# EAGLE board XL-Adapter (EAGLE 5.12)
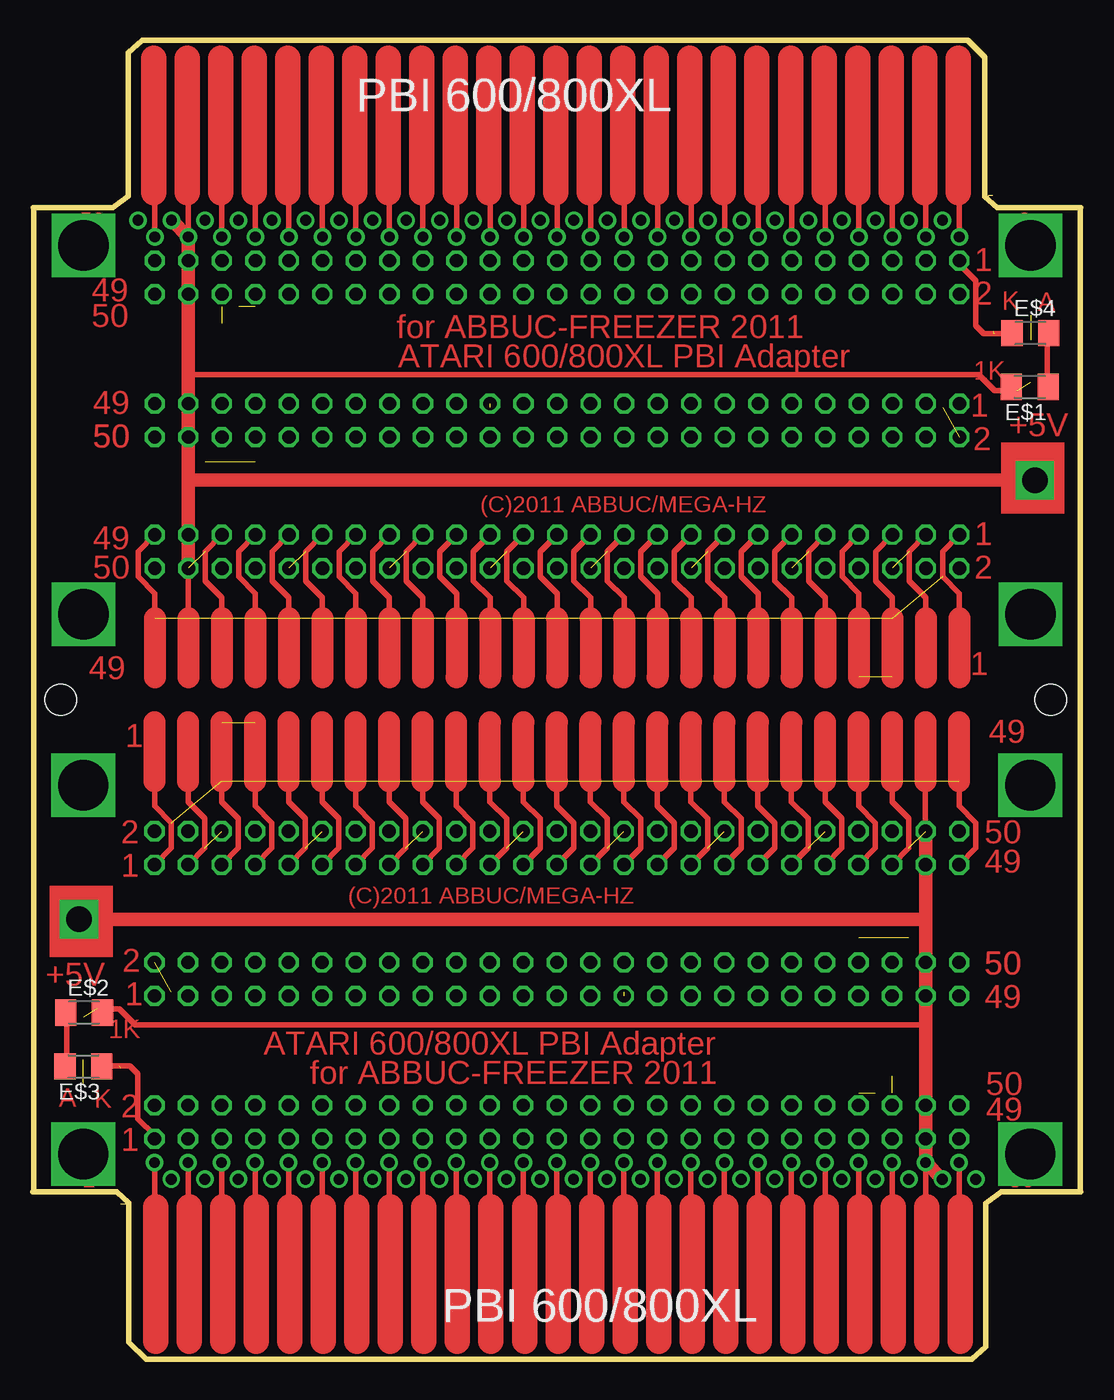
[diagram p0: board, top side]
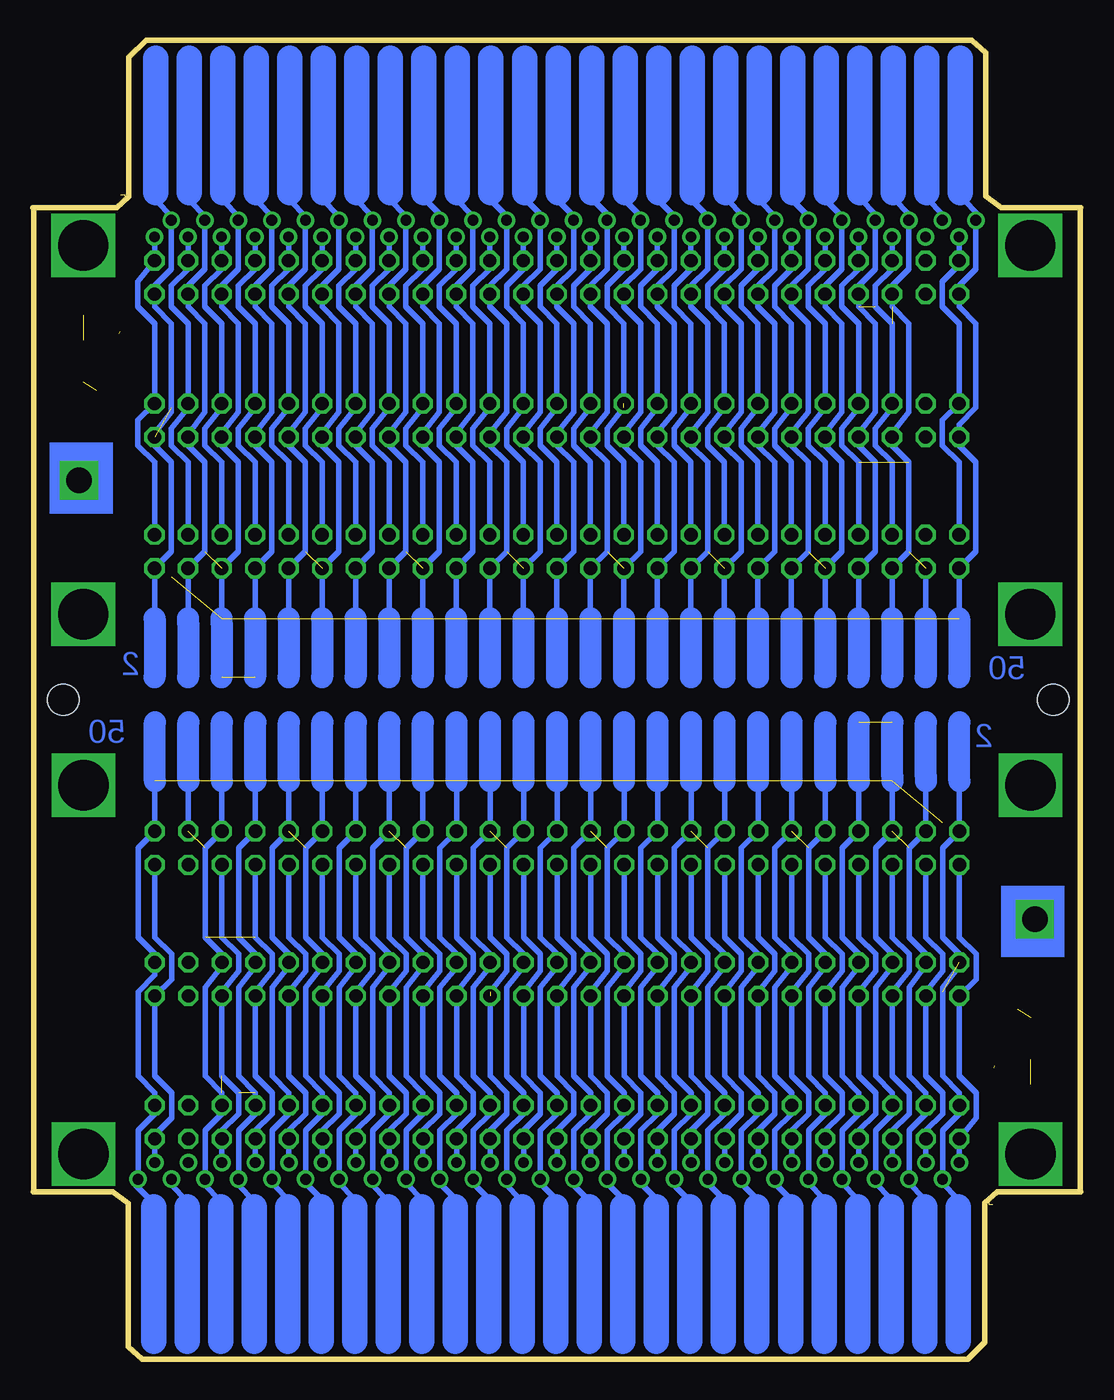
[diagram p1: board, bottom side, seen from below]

Size 79.4 x 100 mm. Coordinates in mm from the lower left corner, seen from the top.
Outline: 79.37,12.7 73.34,12.7 72.18,11.83 72.18,0.95 71.12,0 8.57,0 7.27,1.31 7.27,11.88 6.35,12.7 0,12.7
Outline: 0.02,87.3 6.05,87.3 7.22,88.16 7.22,99.04 8.28,100 70.82,100 72.13,98.69 72.13,88.11 73.04,87.3 79.4,87.3
Outline: 0.05,87.25 0.05,12.75
Outline: 79.35,87.25 79.35,12.75
Copper layers (1*16): Top 0.035mm / dielectric 1.5mm / Bottom 0.035mm
Design rules "ITead_rule": minimum track width 6mil, minimum drill 12mil, track to track 6mil, track to pad 6mil, pad to pad 6mil, via to via 6mil, smd to smd 0mil, copper to edge 10mil, drill to drill 10mil, minimum pad ring 10mil, minimum via ring 6mil, stop-mask expansion 2mil, vias tented up to drill 100mil, thermal gap 10mil
Net classes: 2 3.3: width 0.508 mm, clearance 0.254 mm
Holes 2.4 mm at 2.1,50 77.1,50

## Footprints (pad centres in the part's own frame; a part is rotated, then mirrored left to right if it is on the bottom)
M1206 = smd 1.6 x 2: 1 -1.4,0; 2 1.4,0
XL-PBI = drill 0.813 round: A0 31.115,-8.255; A1 29.845,-6.985; A2 28.575,-8.255; A3 27.305,-6.985; A4 26.035,-8.255; A5 24.765,-6.985; A6 23.495,-8.255; A7 20.955,-8.255; A8 19.685,-6.985; A9 18.415,-8.255; A10 17.145,-6.985; A11 15.875,-8.255; A12 14.605,-6.985; A13 13.335,-8.255; A14 12.065,-6.985; A15 9.525,-6.985; AUDIO -27.305,-8.255; CAS -17.145,-8.255; D0 8.255,-8.255; D1 6.985,-6.985; D2 5.715,-8.255; D3 4.445,-6.985; D4 3.175,-8.255; D5 1.905,-6.985; D6 0.635,-8.255; D7 -0.635,-6.985; EXT.B -13.335,-6.985; EXTSEL 32.385,-6.985; GND -28.575,-6.985; GND2 -18.415,-6.985; GND3 -5.715,-6.985; GND4 -3.175,-6.985; GND5 22.225,-6.985; GND6 33.655,-8.255; GND7 10.795,-8.255; GND8 -1.905,-8.255; GND9 -22.225,-8.255; IRQ -9.525,-8.255; MPD -19.685,-8.255; NC2 -6.985,-8.255; NC3 -12.065,-8.255; NC4 -14.605,-8.255; PHI2 -4.445,-8.255; RAS -20.955,-6.985; RDY -10.795,-6.985; REF -15.875,-6.985; RST -8.255,-6.985; RW -23.495,-6.985; VCC -24.765,-8.255; VCC1 -26.035,-6.985

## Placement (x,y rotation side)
E$1  [M1206]  75.53,73.71 180 top
E$2  [M1206]  3.87,26.29 0 top
E$3  [M1206]  3.82,22.21 180 top
E$4  [M1206]  75.57,77.78 0 top
U$1  XL-PBI  [XL-PBI]  36.53,93.33 0 top
U$3  XL-PBI  [XL-PBI]  42.86,6.67 180 top

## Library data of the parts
E$1-E$4 = rcl
U$1 U$3 = wf-atari

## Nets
N$1: U$3.EXTSEL
N$16: U$3.AUDIO
N$28: U$3.VCC U$3.VCC1
N$32: U$3.GND9
N$33: U$3.MPD
N$34: U$3.CAS
N$35: U$3.NC4
N$37: U$3.NC3
N$38: U$3.IRQ
N$48: U$3.NC2
N$81: U$3.PHI2
N$86: U$1.A2
N$88: U$3.GND8
N$89: U$3.D6
N$90: U$3.D4
N$91: U$3.D2
N$92: U$3.D0
N$93: U$3.GND7
N$94: U$3.A13
N$95: U$3.A11
N$96: U$3.A9
N$97: U$3.A7
N$98: U$3.A6
N$99: U$3.A4
N$102: U$3.RW
N$103: U$3.RAS
N$104: U$3.GND2
N$105: U$3.REF
N$106: U$3.EXT.B
N$107: U$3.RDY
N$108: U$3.RST
N$109: U$3.GND3
N$110: U$3.GND4
N$111: U$3.D7
N$112: U$3.D5
N$113: U$3.D3
N$114: U$3.D1
N$115: U$3.A15
N$116: U$3.A14
N$117: U$3.A12
N$118: U$3.A10
N$119: U$3.A8
N$120: U$3.GND5
N$122: U$3.A5
N$126: U$3.A1 U$3.A3
N$159: U$3.GND6
N$190: U$3.GND
N$238: U$1.A0
N$286: U$1.AUDIO
N$287: U$1.VCC U$1.VCC1
N$288: U$1.GND9
N$289: U$1.MPD
N$290: U$1.CAS
N$291: U$1.NC4
N$292: U$1.NC3
N$293: U$1.IRQ
N$294: U$1.NC2
N$295: U$1.PHI2
N$296: U$1.GND8
N$297: U$1.D6
N$298: U$1.D4
N$299: U$1.D2
N$300: U$1.D0
N$302: U$1.GND7
N$305: U$1.A13
N$306: U$1.A11
N$307: U$3.A2
N$309: U$1.A9
N$318: U$1.A7
N$329: U$1.A6
N$331: U$1.A4
N$334: U$1.EXTSEL
N$354: U$3.A0
N$356: U$1.A1 U$1.A3
N$358: U$1.A5
N$359: U$1.GND5
N$360: U$1.A8
N$361: U$1.A10
N$362: U$1.A12
N$363: U$1.A14
N$364: U$1.A15
N$365: U$1.D1
N$366: U$1.D3
N$367: U$1.D5
N$368: U$1.D7
N$369: U$1.GND4
N$370: U$1.GND3
N$371: U$1.RST
N$372: U$1.RW
N$373: U$1.RAS
N$374: U$1.GND2
N$375: U$1.REF
N$376: U$1.EXT.B
N$377: U$1.RDY
N$402: U$1.GND6
N$426: U$1.GND

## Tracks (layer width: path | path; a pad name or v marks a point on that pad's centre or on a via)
N$1  (via drill 1.02)  (1 unrouted)
  Bottom 0.406: 9.21,46.7 9.21,40.03 10.48,38.76 10.48,32 9.21,30.72 v9.21,30.09 | 10.48,27.87 10.48,21.48 9.21,20.21 v9.21,19.25 9.21,18.62 10.48,17.35 U$3.EXTSEL
N$16  (via drill 1.02)
  Bottom 0.406: U$3.AUDIO v70.17,16.72 70.17,17.03 68.9,18.3 68.9,20.21 70.17,21.48 70.17,27.55 68.9,28.82 68.9,30.72 70.17,32 v70.17,37.49
N$23  (via drill 1.02)
  other vias: 70.17,40.03
N$28  (via drill 1.02)  (1 unrouted)
  Top 0.406: 4.83,26.56 6.54,26.56 7.75,25.35 67.63,25.35 67.65,25.35
  Top 1.016: 67.63,26.91 67.63,25.35 v67.63,19.25 v67.63,16.72 U$3.VCC U$3.VCC1
N$29  (via drill 1.02, 1.93)
  Top 0.406: 67.63,43.52 67.63,43.4 67.6,43.73 67.6,40.46 67.63,37.49
  Top 1.016: v67.63,27.55 v67.63,30.09 67.63,33.36 | 4.13,33.36 3.18,33.36 | 4.13,33.36 67.63,33.36 | v3.49,33.36 4.13,33.36 | 67.63,33.36 67.63,37.49 v67.63,40.03
N$30  (via drill 1.02)
  other vias: 65.09,40.03
N$31  (via drill 1.02)
  other vias: 62.55,40.03
N$32  (via drill 1.02)
  Bottom 0.406: U$3.GND9 v65.09,16.72
N$33  (via drill 1.02)
  Bottom 0.406: U$3.MPD v62.55,16.72
N$34  (via drill 1.02)
  Bottom 0.406: U$3.CAS v60.01,16.72
N$35  (via drill 1.02)
  Bottom 0.406: U$3.NC4 v57.47,16.72
N$36  (via drill 1.02)
  other vias: 60.01,40.03
N$37  (via drill 1.02)
  Bottom 0.406: U$3.NC3 v54.93,16.72
N$38  (via drill 1.02)
  Bottom 0.406: U$3.IRQ v52.39,16.72
N$39  (via drill 1.02)
  other vias: 57.47,40.03
N$40  (via drill 1.02)
  other vias: 54.93,40.03
N$41  (via drill 1.02)
  other vias: 52.39,40.03
N$42  (via drill 1.02)
  other vias: 49.85,40.03
N$43  (via drill 1.02)
  other vias: 47.31,40.03
N$44  (via drill 1.02)
  other vias: 44.77,40.03
N$45  (via drill 1.02)
  other vias: 42.23,40.03
N$46  (via drill 1.02)
  other vias: 39.69,40.03
N$47  (via drill 1.02)
  other vias: 37.15,40.03
N$48  (via drill 1.02)
  Bottom 0.406: U$3.NC2 v49.85,16.72
N$49  (via drill 1.02)
  other vias: 34.61,40.03
N$50  (via drill 1.02)
  other vias: 32.07,40.03
N$51  (via drill 1.02)
  other vias: 29.53,40.03
N$52  (via drill 1.02)
  other vias: 26.99,40.03
N$53  (via drill 1.02)
  other vias: 24.45,40.03
N$54  (via drill 1.02)
  other vias: 21.91,40.03
N$55  (via drill 1.02)
  other vias: 19.37,40.03
N$56  (via drill 1.02)
  other vias: 16.83,40.03
N$57  (via drill 3.81)
  other vias: 75.59,56.47
N$58
  Top 0.406: 19.37,43.84 19.37,42.25 20.64,40.98 20.64,38.76 19.37,37.49
N$59
  Top 0.406: 16.83,37.49 18.1,38.76 18.1,40.66 16.83,41.94 16.83,43.84
N$60
  Top 0.406: 21.91,43.52 21.91,42.25 23.18,40.98 23.18,38.76 21.91,37.49
N$61  (via drill 3.81)
  other vias: 3.83,56.47
N$62
  Top 0.406: 26.99,43.84 26.99,42.25 28.26,40.98 28.26,38.76 26.99,37.49
N$63
  Top 0.406: 24.45,37.49 25.72,38.76 25.72,40.66 24.45,41.94 24.45,43.84
N$64
  Top 0.406: 29.53,43.52 29.53,42.25 30.8,40.98 30.8,38.76 29.53,37.49
N$65  (via drill 3.81)
  other vias: 3.83,84.44
N$66
  Top 0.406: 34.61,43.84 34.61,42.25 35.88,40.98 35.88,38.76 34.61,37.49
N$67
  Top 0.406: 32.07,37.49 33.34,38.76 33.34,40.66 32.07,41.94 32.07,43.84
N$68
  Top 0.406: 37.15,43.52 37.15,42.25 38.42,40.98 38.42,38.76 37.15,37.49
N$69  (via drill 3.81)
  other vias: 75.59,84.44
N$70
  Top 0.406: 42.23,43.84 42.23,42.25 43.5,40.98 43.5,38.76 42.23,37.49
N$71
  Top 0.406: 39.69,37.49 40.96,38.76 40.96,40.66 39.69,41.94 39.69,43.84
N$72
  Top 0.406: 44.77,43.52 44.77,42.25 46.04,40.98 46.04,38.76 44.77,37.49
N$73  (via drill 1.02)
  other vias: 11.77,62.51
N$74
  Top 0.406: 49.85,43.84 49.85,42.25 51.12,40.98 51.12,38.76 49.85,37.49
N$75
  Top 0.406: 47.31,37.49 48.58,38.76 48.58,40.66 47.31,41.94 47.31,43.84
N$76
  Top 0.406: 52.39,43.52 52.39,42.25 53.66,40.98 53.66,38.76 52.39,37.49
N$77  (via drill 1.02)
  Bottom 0.406: 54.95,83.28 54.95,82.64 56.22,81.38 56.22,79.79 54.95,78.52 54.95,72.44 | 54.95,72.44 54.95,72.76 | 54.95,72.44 54.95,72.13 56.22,70.54 56.22,69.27 54.95,68 v54.95,62.51
N$78
  Top 0.406: 57.47,43.84 57.47,42.25 58.74,40.98 58.74,38.76 57.47,37.49
N$79  (via drill 1.02)
  Bottom 0.406: 60.03,83.28 60.03,82.64 61.3,81.38 61.3,79.79 60.03,78.52 60.03,72.13 61.3,70.54 61.3,69.27 60.03,68 v60.03,62.51
N$80
  Top 0.406: 54.93,37.49 56.2,38.76 56.2,40.66 54.93,41.94 54.93,43.84
N$81  (via drill 1.02)
  Bottom 0.406: U$3.PHI2 v47.31,16.72
N$82
  Top 0.406: 60.01,43.52 60.01,42.25 61.28,40.98 61.28,38.76 60.01,37.49
N$83  (via drill 1.02)
  Top 0.406: 67.65,56.16 67.65,57.74 66.38,59.01 66.38,61.24 v67.65,62.51
  Top 1.676: 67.65,56.16 67.65,51.71
N$84
  Top 0.406: 65.09,43.84 65.09,42.25 66.36,40.98 66.36,38.76 65.09,37.49
N$85
  Top 0.406: 62.55,37.49 63.82,38.76 63.82,40.66 62.55,41.94 62.55,43.84
N$86  (via drill 1.02)
  Top 0.406: 65.11,56.47 65.11,57.74 63.84,59.01 63.84,61.24 v65.11,62.51
  Bottom 0.406: 65.11,62.82 v65.11,62.51 65.11,68 66.38,69.27 66.38,70.54 65.11,72.13 65.11,72.44 | U$1.A2 v65.11,83.28 65.11,82.64 66.38,81.38 66.38,79.79 65.11,78.52 65.11,72.44 | 65.11,72.44 65.11,72.76
N$87
  Top 0.406: 70.17,37.49 71.44,38.76 71.44,40.66 70.17,41.94 70.17,43.84
N$88  (via drill 1.02)
  Bottom 0.406: U$3.GND8 v44.77,16.72
N$89  (via drill 1.02)
  Bottom 0.406: U$3.D6 v42.23,16.72
N$90  (via drill 1.02)
  Bottom 0.406: U$3.D4 v39.69,16.72
N$91  (via drill 1.02)
  Bottom 0.406: U$3.D2 v37.15,16.72
N$92  (via drill 1.02)
  Bottom 0.406: U$3.D0 v34.61,16.72
N$93  (via drill 1.02)
  Bottom 0.406: U$3.GND7 v32.07,16.72
N$94  (via drill 1.02)
  Bottom 0.406: U$3.A13 v29.53,16.72
N$95  (via drill 1.02)
  Bottom 0.406: U$3.A11 v26.99,16.72
N$96  (via drill 1.02)
  Bottom 0.406: U$3.A9 v24.45,16.72
N$97  (via drill 1.02)
  Bottom 0.406: U$3.A7 v21.91,16.72
N$98  (via drill 1.02)
  Bottom 0.406: U$3.A6 v19.37,16.72
N$99  (via drill 1.02)
  Bottom 0.406: U$3.A4 v16.83,16.72 16.83,17.35 15.56,18.62 15.56,20.21 16.83,21.48 16.83,27.87 15.56,29.45 15.56,30.72 16.83,32 v16.83,37.49
N$100  (via drill 1.02)
  other vias: 9.23,72.44
N$101  (via drill 1.02)
  other vias: 14.31,72.44
N$102
  Bottom 0.406: U$3.RW 66.36,17.35
N$103
  Bottom 0.406: U$3.RAS 63.82,17.35
N$104
  Bottom 0.406: U$3.GND2 61.28,17.35
N$105
  Bottom 0.406: U$3.REF 58.74,17.35
N$106
  Bottom 0.406: U$3.EXT.B 56.2,17.35
N$107
  Bottom 0.406: U$3.RDY 53.66,17.35
N$108
  Bottom 0.406: U$3.RST 51.12,17.35
N$109
  Bottom 0.406: U$3.GND3 48.58,17.35
N$110
  Bottom 0.406: U$3.GND4 46.04,17.35
N$111
  Bottom 0.406: U$3.D7 43.5,17.35
N$112
  Bottom 0.406: U$3.D5 40.96,17.35
N$113
  Bottom 0.406: U$3.D3 38.42,17.35
N$114
  Bottom 0.406: U$3.D1 35.88,17.35
N$115
  Bottom 0.406: U$3.A15 33.34,17.35
N$116
  Bottom 0.406: U$3.A14 30.8,17.35
N$117
  Bottom 0.406: U$3.A12 28.26,17.35
N$118
  Bottom 0.406: U$3.A10 25.72,17.35
N$119
  Bottom 0.406: U$3.A8 23.18,17.35
N$120
  Bottom 0.406: U$3.GND5 20.64,17.35
N$121  (via drill 1.02)
  other vias: 16.85,72.44
N$122
  Bottom 0.406: U$3.A5 18.1,17.35
N$123
  Bottom 0.406: 18.1,13.65 18.1,17.35 16.83,18.62 16.83,20.21 18.1,21.48
N$124  (via drill 1.02)
  other vias: 19.39,72.44
N$125
  Bottom 0.406: 20.64,13.65 20.64,17.35 19.37,18.62 19.37,20.21 20.64,21.48
N$126  (via drill 1.02)  (23 unrouted)
  Bottom 0.406: U$3.A1 13.02,17.35 11.75,18.62 v11.75,19.25 11.75,20.21 13.02,21.48 13.02,28.18 11.73,29.94 11.75,30.72 13.02,32 13.02,38.76 v11.75,40.03 11.75,44.16 | 14.29,44.16 v14.29,40.03 15.56,38.76 15.56,32 14.29,30.72 14.29,29.77 15.56,28.18 15.56,21.48 14.29,20.21 v14.29,19.25 14.29,18.62 15.56,17.35 U$3.A3
  Bottom 1.676: 70.17,43.84 70.17,48.28 | 67.63,43.84 67.63,48.28 | 65.09,43.84 65.09,48.28 | 62.55,43.84 62.55,48.28 | 60.01,43.84 60.01,48.28 | 57.47,43.84 57.47,48.28 | 54.93,43.84 54.93,48.28 | 52.39,43.84 52.39,48.28 | 49.85,43.84 49.85,48.28 | 47.31,43.84 47.31,48.28 | 44.77,43.84 44.77,48.28 | 42.23,43.84 42.23,48.28 | 39.69,43.84 39.69,48.28 | 37.15,43.84 37.15,48.28 | 34.61,43.84 34.61,48.28 | 32.07,43.84 32.07,48.28 | 29.53,43.84 29.53,48.28 | 26.99,43.84 26.99,48.28 | 24.45,43.84 24.45,48.28 | 21.91,43.84 21.91,48.28 | 19.37,43.84 19.37,48.28 | 16.83,43.84 16.83,48.28 | 11.75,43.84 11.75,44.16 11.75,48.28 | 14.29,43.84 14.29,44.16 14.29,48.28
N$127  (via drill 1.02)
  other vias: 21.93,72.44
N$128  (via drill 1.02)
  other vias: 24.47,72.44
N$129
  Bottom 0.406: 23.18,13.65 23.18,17.35 21.91,18.62 21.91,20.21 23.18,21.48
N$130
  Bottom 0.406: 25.72,13.65 25.72,17.35 24.45,18.62 24.45,20.21 25.72,21.48
N$131  (via drill 1.02)
  other vias: 27.01,72.44
N$132  (via drill 1.02)
  Bottom 0.406: 29.53,16.72 29.53,17.35 28.26,18.62 28.26,20.21 29.53,21.48 29.53,27.87 28.26,29.45 28.26,30.72 29.53,32 v29.53,37.49
N$133
  Bottom 0.406: 28.26,13.65 28.26,17.35 26.99,18.62 26.99,20.21 28.26,21.48
N$134
  Bottom 0.406: 30.8,13.65 30.8,17.35 29.53,18.62 29.53,20.21 30.8,21.48
N$135  (via drill 1.02)
  other vias: 29.55,72.44
N$136  (via drill 1.02)
  other vias: 32.09,72.44
N$137
  Bottom 0.406: 33.34,13.65 33.34,17.35 32.07,18.62 32.07,20.21 33.34,21.48
N$138
  Bottom 0.406: 35.88,13.65 35.88,17.35 34.61,18.62 34.61,20.21 35.88,21.48
N$139  (via drill 1.02)
  other vias: 37.17,72.44
N$140  (via drill 1.02)
  Bottom 0.406: 39.69,16.72 39.69,17.35 38.42,18.62 38.42,20.21 39.69,21.48 39.69,27.87 38.42,29.45 38.42,30.72 39.69,32 v39.69,37.49
N$141
  Bottom 0.406: 38.42,13.65 38.42,17.35 37.15,18.62 37.15,20.21 38.42,21.48
N$142
  Bottom 0.406: 40.96,13.65 40.96,17.35 39.69,18.62 39.69,20.21 40.96,21.48
N$143  (via drill 1.02)
  other vias: 39.71,72.44
N$144  (via drill 1.02)  (1 unrouted)
  Bottom 0.406: 44.77,16.72 44.77,17.35 43.5,18.62 43.5,20.21 44.77,21.48 44.77,27.87 43.5,29.45 43.5,30.72 44.77,32 v44.77,37.49
  other vias: 44.77,27.55
N$145
  Bottom 0.406: 43.5,13.65 43.5,17.35 42.23,18.62 42.23,20.21 43.5,21.48
N$146
  Bottom 0.406: 46.04,13.65 46.04,17.35 44.77,18.62 44.77,20.21 46.04,21.48
N$147  (via drill 1.02)
  other vias: 42.25,72.44
N$148  (via drill 1.02)
  Bottom 0.406: 49.85,16.72 49.85,17.35 48.58,18.62 48.58,20.21 49.85,21.48 49.85,27.87 48.58,29.45 48.58,30.72 49.85,32 v49.85,37.49
N$149
  Bottom 0.406: 48.58,13.65 48.58,17.35 47.31,18.62 47.31,20.21 48.58,21.48
N$150
  Bottom 0.406: 51.12,13.65 51.12,17.35 49.85,18.62 49.85,20.21 51.12,21.48
N$151  (via drill 1.02)
  other vias: 44.79,72.44
N$152  (via drill 1.02)
  Bottom 0.406: 54.93,16.72 54.93,17.35 53.66,18.62 53.66,20.21 54.93,21.48 54.93,27.87 53.66,29.45 53.66,30.72 54.93,32 v54.93,37.49
N$153
  Bottom 0.406: 53.66,13.65 53.66,17.35 52.39,18.62 52.39,20.21 53.66,21.48
N$154
  Bottom 0.406: 56.2,13.65 56.2,17.35 54.93,18.62 54.93,20.21 56.2,21.48
N$155  (via drill 1.02)
  other vias: 47.33,72.44
N$156  (via drill 1.02)
  Bottom 0.406: 60.01,16.72 60.01,17.35 58.74,18.62 58.74,20.21 60.01,21.48 60.01,27.87 58.74,29.45 58.74,30.72 60.01,32 v60.01,37.49
N$157
  Bottom 0.406: 58.74,13.65 58.74,17.35 57.47,18.62 57.47,20.21 58.74,21.48
N$158
  Bottom 0.406: 61.28,13.65 61.28,17.35 60.01,18.62 60.01,20.21 61.28,21.48
N$159  (via drill 1.02)  (24 unrouted)
  Top 0.406: v9.21,37.49 10.48,38.76 10.48,40.66 9.21,41.94 9.21,43.84 | v9.21,16.72 9.21,16.99 7.95,18.25 7.95,21.65 7.35,22.25 6.55,22.25 5.25,22.25
  Top 1.676: 9.21,43.84 9.21,48.28 | 14.29,43.84 14.29,48.28 | 16.83,43.84 16.83,48.28 | 19.37,43.84 19.37,48.28 | 21.91,43.84 21.91,48.28 | 24.45,43.84 24.45,48.28 | 26.99,43.84 26.99,48.28 | 29.53,43.84 29.53,48.28 | 32.07,43.84 32.07,48.28 | 34.61,43.84 34.61,48.28 | 37.15,43.84 37.15,48.28 | 39.69,43.84 39.69,48.28 | 42.23,43.84 42.23,48.28 | 44.77,43.84 44.77,48.28 | 47.31,43.84 47.31,48.28 | 49.85,43.84 49.85,48.28 | 52.39,43.84 52.39,48.28 | 54.93,43.84 54.93,48.28 | 57.47,43.84 57.47,48.28 | 60.01,43.84 60.01,48.28 | 62.55,43.84 62.55,48.28 | 65.09,43.84 65.09,48.28 | 67.63,43.84 67.63,48.28 | 70.17,43.84 70.17,48.28
  Bottom 0.406: 9.21,32 9.21,37.17 | 7.94,30.72 7.94,29.14 | 9.21,26.96 9.21,27.19 | 9.21,32 v9.21,37.49 | 7.94,30.72 9.21,32 | 7.94,30.72 7.94,28.82 v9.21,27.55 9.21,26.96 | 9.21,26.96 9.21,21.48 7.94,20.21 7.94,18.3 v9.21,16.72 U$3.GND6
N$160
  Bottom 0.406: 11.75,27.23 11.75,27.87 10.48,29.45 10.48,30.72 11.75,32 11.75,37.17
N$161  (via drill 1.02)
  other vias: 49.87,72.44
N$162
  Top 1.016: 67.63,27.23 67.63,29.77
N$163  (via drill 1.02)
  other vias: 52.41,72.44
N$164  (via drill 1.02)
  other vias: 54.95,72.44
N$165  (via drill 1.02)
  other vias: 57.49,72.44
N$166
  Bottom 0.406: 10.48,38.44 10.48,32 9.21,30.72 9.21,29.77 10.48,28.18 10.48,25.92
N$167  (via drill 1.02)
  other vias: 60.03,72.44
N$168  (via drill 1.02)
  other vias: 62.57,72.44
N$169
  Bottom 0.406: 18.1,21.48 18.1,27.87
N$170
  Bottom 0.406: 20.64,21.48 20.64,27.87
N$171
  Bottom 0.406: 23.18,21.48 23.18,27.87
N$172
  Bottom 0.406: 25.72,21.48 25.72,27.87
N$173
  Bottom 0.406: 28.26,21.48 28.26,27.87
N$174
  Bottom 0.406: 30.8,21.48 30.8,27.87
N$175
  Bottom 0.406: 33.34,21.48 33.34,27.87
N$176
  Bottom 0.406: 35.88,21.48 35.88,27.87
N$177
  Bottom 0.406: 38.42,21.48 38.42,27.87
N$178
  Bottom 0.406: 40.96,21.48 40.96,27.87
N$179
  Bottom 0.406: 43.5,21.48 43.5,27.87
N$180
  Bottom 0.406: 46.04,21.48 46.04,27.87
N$181
  Bottom 0.406: 48.58,21.48 48.58,27.87
N$182  (via drill 1.02)
  other vias: 11.75,30.09
N$183
  Bottom 0.406: 51.12,21.48 51.12,27.87
N$184
  Bottom 0.406: 66.36,21.48 66.36,28.18
N$185
  Bottom 0.406: 63.82,21.48 63.82,28.18
N$186
  Bottom 0.406: 61.28,21.48 61.28,27.87
N$187
  Bottom 0.406: 58.74,21.48 58.74,27.87
N$188
  Bottom 0.406: 56.2,21.48 56.2,27.87
N$189
  Bottom 0.406: 53.66,21.48 53.66,27.87
N$190
  Bottom 0.406: U$3.GND 71.44,17.35 70.17,18.62 70.17,20.21 71.44,21.48 71.44,27.87 70.17,29.14 70.17,30.72 71.44,32 71.44,38.76 70.17,40.03 70.17,46.7
N$191  (via drill 1.02)
  Bottom 0.406: 21.91,16.72 21.91,17.35 20.64,18.62 20.64,20.21 21.91,21.48 21.91,27.87 20.64,29.45 20.64,30.72 21.91,32 v21.91,37.49
N$192  (via drill 1.02)
  other vias: 65.11,72.44
N$193
  Bottom 0.406: 18.1,21.48 18.1,28.18 16.83,29.77 16.83,30.72 18.1,32 18.1,38.76 16.83,40.03 16.83,46.7
N$194  (via drill 1.02)
  other vias: 9.23,69.91
N$195  (via drill 1.02)
  Bottom 0.406: 26.99,16.72 26.99,17.35 25.72,18.62 25.72,20.21 26.99,21.48 26.99,27.87 25.72,29.45 25.72,30.72 26.99,32 v26.99,37.49
N$196  (via drill 1.02)
  other vias: 14.31,69.91
N$197  (1 unrouted)
  Bottom 0.406: 23.18,21.48 23.18,28.18 21.91,29.77 21.91,30.72 23.18,32 23.18,38.76 21.91,40.03 21.91,44.16 | 20.64,21.48 20.64,28.18 19.37,29.77 19.37,30.72 20.64,32 20.64,38.76 19.37,40.03 19.37,44.16
N$198
  Bottom 0.406: 25.72,21.48 25.72,28.18 24.45,29.77 24.45,30.72 25.72,32 25.72,38.76 24.45,40.03 24.45,46.7
N$199  (via drill 1.02)
  Bottom 0.406: 32.07,16.72 32.07,17.35 30.8,18.62 30.8,20.21 32.07,21.48 32.07,27.87 30.8,29.45 30.8,30.72 32.07,32 v32.07,37.49
N$200  (via drill 1.02)
  other vias: 16.85,69.91
N$201  (via drill 1.02)
  other vias: 19.39,69.91
N$202  (1 unrouted)
  Bottom 0.406: 30.8,21.48 30.8,28.18 29.53,29.77 29.53,30.72 30.8,32 30.8,38.76 29.53,40.03 29.53,44.16 | 28.26,21.48 28.26,28.18 26.99,29.77 26.99,30.72 28.26,32 28.26,38.76 26.99,40.03 26.99,44.16
N$203  (via drill 1.02)
  Bottom 0.406: 37.15,16.72 37.15,17.35 35.88,18.62 35.88,20.21 37.15,21.48 37.15,27.87 35.88,29.45 35.88,30.72 37.15,32 v37.15,37.49
N$204  (via drill 1.02)
  Bottom 0.406: 34.61,16.72 34.61,17.35 33.34,18.62 33.34,20.21 34.61,21.48 34.61,27.87 33.34,29.45 33.34,30.72 34.61,32 v34.61,37.49
N$205
  Bottom 0.406: 33.34,21.48 33.34,28.18 32.07,29.77 32.07,30.72 33.34,32 33.34,38.76 32.07,40.03 32.07,46.7
N$206  (via drill 1.02)
  other vias: 21.93,69.91
N$207  (via drill 1.02)
  Bottom 0.406: 42.23,16.72 42.23,17.35 40.96,18.62 40.96,20.21 42.23,21.48 42.23,27.87 40.96,29.45 40.96,30.72 42.23,32 v42.23,37.49
N$208  (via drill 1.02)
  other vias: 24.47,69.91
N$209  (1 unrouted)
  Bottom 0.406: 38.42,21.48 38.42,28.18 37.15,29.77 37.15,30.72 38.42,32 38.42,38.76 37.15,40.03 37.15,44.16 | 35.88,21.48 35.88,28.18 34.61,29.77 34.61,30.72 35.88,32 35.88,38.76 34.61,40.03 34.61,44.16
N$210
  Bottom 0.406: 40.96,21.48 40.96,28.18 39.69,29.77 39.69,30.72 40.96,32 40.96,38.76 39.69,40.03 39.69,46.7
N$211  (via drill 1.02)
  Bottom 0.406: 47.31,16.72 47.31,17.35 46.04,18.62 46.04,20.21 47.31,21.48 47.31,27.87 46.04,29.45 46.04,30.72 47.31,32 v47.31,37.49
N$212  (via drill 1.02)
  other vias: 27.01,69.91
N$213  (via drill 1.02)
  other vias: 29.55,69.91
N$214  (1 unrouted)
  Bottom 0.406: 46.04,21.48 46.04,28.18 44.77,29.77 44.77,30.72 46.04,32 46.04,38.76 44.77,40.03 44.77,44.16 | 43.5,21.48 43.5,28.18 42.23,29.77 42.23,30.72 43.5,32 43.5,38.76 42.23,40.03 42.23,44.16
N$215  (via drill 1.02)
  Bottom 0.406: 52.39,16.72 52.39,17.35 51.12,18.62 51.12,20.21 52.39,21.48 52.39,27.87 51.12,29.45 51.12,30.72 52.39,32 v52.39,37.49
N$216  (via drill 1.02)
  other vias: 32.09,69.91
N$217
  Bottom 0.406: 48.58,21.48 48.58,28.18 46.99,30.09 47.31,30.72 48.58,32 48.58,38.76 47.31,40.03 47.31,46.7
N$218  (via drill 1.02)
  other vias: 34.63,69.91
N$219  (via drill 1.02)
  Bottom 0.406: 57.47,27.55 57.47,27.23 | 57.47,27.55 57.47,27.87 56.2,29.45 56.2,30.72 57.47,32 v57.47,37.49 | 57.47,16.72 57.47,17.35 56.2,18.62 56.2,20.21 57.47,21.48 57.47,27.55
N$220  (via drill 1.02)
  other vias: 37.17,69.91
N$221  (1 unrouted)
  Bottom 0.406: 53.66,21.48 53.66,28.18 52.39,29.77 52.39,30.72 53.66,32 53.66,38.76 52.39,40.03 52.39,44.16 | 51.12,21.48 51.12,28.18 49.85,29.77 49.85,30.72 51.12,32 51.12,38.76 49.85,40.03 49.85,44.16
N$222
  Bottom 0.406: 56.2,21.48 56.2,28.18 54.93,29.77 54.93,30.72 56.2,32 56.2,38.76 54.93,40.03 54.93,46.7
N$223  (via drill 1.02)  (6 unrouted)
  Bottom 0.406: 63.82,28.18 62.55,29.77 62.55,30.72 63.82,32 63.82,38.76 62.55,40.03 62.55,46.7 | 66.36,28.18 65.09,29.77 65.09,30.72 66.36,32 66.36,38.76 65.09,40.03 65.09,44.16 | 62.55,16.72 62.55,17.35 61.28,18.62 61.28,20.21 62.55,21.48 62.55,27.87 61.28,29.45 61.28,30.72 62.55,32 v62.55,37.49 | 63.82,17.35 62.55,18.62 62.55,20.21 63.82,21.48 | 65.09,17.35 63.82,18.62 63.82,20.21 65.09,21.48 65.09,27.87 63.82,29.45 63.82,30.72 65.09,32 v65.09,37.49 | 66.36,17.35 65.09,18.62 65.09,20.21 66.36,21.48 | 67.63,40.03 67.63,44.16
N$224  (via drill 1.02)
  other vias: 39.71,69.91
N$225  (via drill 1.02)
  other vias: 42.25,69.91
N$226  (1 unrouted)
  Bottom 0.406: 61.28,21.48 61.28,28.18 60.01,29.77 60.01,30.72 61.28,32 61.28,38.76 60.01,40.03 60.01,44.16 | 58.74,21.48 58.74,28.18 57.47,29.77 57.47,30.72 58.74,32 58.74,38.76 57.47,40.03 57.47,44.16
N$227  (via drill 1.02)
  other vias: 44.79,69.91
N$228  (via drill 1.02)
  other vias: 47.33,69.91
N$229  (via drill 1.02)
  other vias: 49.87,69.91
N$230  (via drill 1.02)
  other vias: 52.41,69.91
N$231  (via drill 3.81)
  other vias: 3.81,43.52
N$232  (via drill 3.81)
  other vias: 75.57,43.52
N$233  (via drill 3.81)
  other vias: 75.57,15.56
N$234  (via drill 3.81)
  other vias: 3.81,15.56
N$235  (via drill 1.02)
  other vias: 54.95,69.91
N$236  (via drill 1.02)
  other vias: 57.49,69.91
N$237  (via drill 1.02)
  other vias: 60.03,69.91
N$238  (via drill 1.02)
  Bottom 0.406: U$1.A0 v67.65,83.28 67.65,82.64 68.92,81.38 68.92,79.79 67.65,78.52 v67.65,72.44
N$239  (via drill 1.02)
  other vias: 62.57,69.91
N$240  (via drill 1.02)
  other vias: 65.11,69.91
N$241  (via drill 1.02)
  other vias: 67.65,69.91
N$242  (via drill 1.02)
  other vias: 9.23,59.96
N$243  (via drill 1.02, 1.93)
  Top 0.406: 11.77,56.47 11.77,56.59 11.75,57.01 11.75,61.03 11.77,62.51
  Top 1.016: v11.77,72.44 v11.77,69.91 11.77,66.63 | 75.27,66.63 76.22,66.63 | 75.27,66.63 11.77,66.63 | v75.9,66.63 75.27,66.63 | 11.77,66.63 11.77,62.51 v11.77,59.96
N$244  (via drill 1.02)
  other vias: 14.31,59.96
N$245  (via drill 1.02)
  other vias: 16.85,59.96
N$246  (via drill 1.02)
  other vias: 19.39,59.96
N$247  (via drill 1.02)
  other vias: 21.93,59.96
N$248  (via drill 1.02)
  other vias: 24.47,59.96
N$249  (via drill 1.02)
  other vias: 27.01,59.96
N$250  (via drill 1.02)
  other vias: 29.55,59.96
N$251  (via drill 1.02)
  other vias: 32.09,59.96
N$252  (via drill 1.02)
  other vias: 34.63,59.96
N$253  (via drill 1.02)
  other vias: 37.17,59.96
N$254  (via drill 1.02)
  other vias: 39.71,59.96
N$255  (via drill 1.02)
  other vias: 42.25,59.96
N$256  (via drill 1.02)
  other vias: 44.79,59.96
N$257  (via drill 1.02)
  other vias: 47.33,59.96
N$258  (via drill 1.02)
  other vias: 49.87,59.96
N$259  (via drill 1.02)
  other vias: 52.41,59.96
N$260  (via drill 1.02)
  other vias: 54.95,59.96
N$261  (via drill 1.02)
  other vias: 57.49,59.96
N$262  (via drill 1.02)
  other vias: 60.03,59.96
N$263  (via drill 1.02)
  other vias: 62.57,59.96
N$264
  Top 0.406: 60.03,56.16 60.03,57.74 58.76,59.01 58.76,61.24 60.03,62.51
N$265
  Top 0.406: 62.57,62.51 61.3,61.24 61.3,59.33 62.57,58.06 62.57,56.16
N$266
  Top 0.406: 57.49,56.47 57.49,57.74 56.22,59.01 56.22,61.24 57.49,62.51
N$267
  Top 0.406: 52.41,56.16 52.41,57.74 51.14,59.01 51.14,61.24 52.41,62.51
N$268
  Top 0.406: 54.95,62.51 53.68,61.24 53.68,59.33 54.95,58.06 54.95,56.16
N$269
  Top 0.406: 49.87,56.47 49.87,57.74 48.6,59.01 48.6,61.24 49.87,62.51
N$270
  Top 0.406: 44.79,56.16 44.79,57.74 43.52,59.01 43.52,61.24 44.79,62.51
N$271
  Top 0.406: 47.33,62.51 46.06,61.24 46.06,59.33 47.33,58.06 47.33,56.16
N$272
  Top 0.406: 42.25,56.47 42.25,57.74 40.98,59.01 40.98,61.24 42.25,62.51
N$273
  Top 0.406: 37.17,56.16 37.17,57.74 35.9,59.01 35.9,61.24 37.17,62.51
N$274
  Top 0.406: 39.71,62.51 38.44,61.24 38.44,59.33 39.71,58.06 39.71,56.16
N$275
  Top 0.406: 34.63,56.47 34.63,57.74 33.36,59.01 33.36,61.24 34.63,62.51
N$276
  Top 0.406: 29.55,56.16 29.55,57.74 28.28,59.01 28.28,61.24 29.55,62.51
N$277
  Top 0.406: 32.09,62.51 30.82,61.24 30.82,59.33 32.09,58.06 32.09,56.16
N$278
  Top 0.406: 27.01,56.47 27.01,57.74 25.74,59.01 25.74,61.24 27.01,62.51
N$279
  Top 0.406: 21.93,56.16 21.93,57.74 20.66,59.01 20.66,61.24 21.93,62.51
N$280
  Top 0.406: 24.47,62.51 23.2,61.24 23.2,59.33 24.47,58.06 24.47,56.16
N$281
  Top 0.406: 19.39,56.47 19.39,57.74 18.12,59.01 18.12,61.24 19.39,62.51
N$282
  Top 0.406: 14.31,56.16 14.31,57.74 13.04,59.01 13.04,61.24 14.31,62.51
N$283
  Top 0.406: 16.85,62.51 15.58,61.24 15.58,59.33 16.85,58.06 16.85,56.16
N$284  (via drill 1.02)
  other vias: 67.63,37.49
N$285
  Top 0.406: 9.23,62.51 7.96,61.24 7.96,59.33 9.23,58.06 9.23,56.16
N$286  (via drill 1.02)
  Bottom 0.406: U$1.AUDIO v9.23,83.28 9.23,82.96 10.5,81.69 10.5,79.79 9.23,78.52 9.23,72.44 10.5,71.17 10.5,69.27 9.23,68 v9.23,62.51
N$287  (via drill 1.02)  (1 unrouted)
  Top 0.406: 74.57,73.44 72.86,73.44 71.65,74.65 11.77,74.65 11.75,74.65
  Top 1.016: 11.77,73.08 11.77,74.65 v11.77,80.74 v11.77,83.28 U$1.VCC U$1.VCC1
N$288  (via drill 1.02)
  Bottom 0.406: U$1.GND9 v14.31,83.28
N$289  (via drill 1.02)
  Bottom 0.406: U$1.MPD v16.85,83.28
N$290  (via drill 1.02)
  Bottom 0.406: U$1.CAS v19.39,83.28
N$291  (via drill 1.02)
  Bottom 0.406: U$1.NC4 v21.93,83.28
N$292  (via drill 1.02)
  Bottom 0.406: U$1.NC3 v24.47,83.28
N$293  (via drill 1.02)
  Bottom 0.406: U$1.IRQ v27.01,83.28
N$294  (via drill 1.02)
  Bottom 0.406: U$1.NC2 v29.55,83.28
N$295  (via drill 1.02)
  Bottom 0.406: U$1.PHI2 v32.09,83.28
N$296  (via drill 1.02)
  Bottom 0.406: U$1.GND8 v34.63,83.28
N$297  (via drill 1.02)
  Bottom 0.406: U$1.D6 v37.17,83.28
N$298  (via drill 1.02)
  Bottom 0.406: U$1.D4 v39.71,83.28
N$299  (via drill 1.02)
  Bottom 0.406: U$1.D2 v42.25,83.28
N$300  (via drill 1.02)
  Bottom 0.406: U$1.D0 v44.79,83.28
N$301  (via drill 1.02)
  Bottom 0.406: 24.45,16.72 24.45,17.35 23.18,18.62 23.18,20.21 24.45,21.48 24.45,27.55 | 24.45,27.55 24.45,27.23 | 24.45,27.55 24.45,27.87 23.18,29.45 23.18,30.72 24.45,32 v24.45,37.49
N$302  (via drill 1.02)
  Bottom 0.406: U$1.GND7 v47.33,83.28
N$303  (via drill 1.02)
  Bottom 0.406: 19.37,16.72 19.37,17.35 18.1,18.62 18.1,20.21 19.37,21.48 19.37,27.87 18.1,29.45 18.1,30.72 19.37,32 v19.37,37.49
N$304  (via drill 1.02)
  Top 0.406: 11.75,43.84 11.75,42.25 13.02,40.98 13.02,38.76 v11.75,37.49
  Top 1.676: 11.75,43.84 11.75,48.28
N$305  (via drill 1.02)
  Bottom 0.406: U$1.A13 v49.87,83.28
N$306  (via drill 1.02)
  Bottom 0.406: U$1.A11 v52.41,83.28
N$307  (via drill 1.02)
  Top 0.406: 14.29,43.52 14.29,42.25 15.56,40.98 15.56,38.76 v14.29,37.49
  Bottom 0.406: 14.29,37.17 v14.29,37.49 14.29,32 13.02,30.72 13.02,29.45 14.29,27.87 14.29,27.55 | U$3.A2 v14.29,16.72 14.29,17.35 13.02,18.62 13.02,20.21 14.29,21.48 14.29,27.55 | 14.29,27.55 14.29,27.23
N$308  (via drill 1.02)
  other vias: 70.17,27.55
N$309  (via drill 1.02)
  Bottom 0.406: U$1.A9 v54.95,83.28
N$310  (via drill 1.02)
  other vias: 65.09,27.55
N$311  (via drill 1.02)
  other vias: 62.55,27.55
N$312  (via drill 1.02)
  other vias: 60.01,27.55
N$313  (via drill 1.02)
  other vias: 57.47,27.55
N$314  (via drill 1.02)
  other vias: 54.93,27.55
N$315  (via drill 1.02)
  other vias: 52.39,27.55
N$316  (via drill 1.02)
  other vias: 49.85,27.55
N$317  (via drill 1.02)
  other vias: 47.31,27.55
N$318  (via drill 1.02)
  Bottom 0.406: U$1.A7 v57.49,83.28
N$319  (via drill 1.02)
  other vias: 42.23,27.55
N$320  (via drill 1.02)
  other vias: 39.69,27.55
N$321  (via drill 1.02)
  other vias: 37.15,27.55
N$322  (via drill 1.02)
  other vias: 34.61,27.55
N$323  (via drill 1.02)
  other vias: 32.07,27.55
N$324  (via drill 1.02)
  other vias: 29.53,27.55
N$325  (via drill 1.02)
  other vias: 26.99,27.55
N$326  (via drill 1.02)
  other vias: 24.45,27.55
N$327  (via drill 1.02)
  other vias: 21.91,27.55
N$328  (via drill 1.02)
  other vias: 19.37,27.55
N$329  (via drill 1.02)
  Bottom 0.406: U$1.A6 v60.03,83.28
N$330  (via drill 1.02)
  other vias: 16.83,27.55
N$331  (via drill 1.02)
  Bottom 0.406: U$1.A4 v62.57,83.28 62.57,82.64 63.84,81.38 63.84,79.79 62.57,78.52 62.57,72.13 63.84,70.54 63.84,69.27 62.57,68 v62.57,62.51
N$332  (via drill 1.02)
  other vias: 14.29,27.55
N$333  (via drill 1.02)
  other vias: 70.17,30.09
N$334  (via drill 1.02)  (1 unrouted)
  Bottom 0.406: 70.19,53.3 70.19,59.96 68.92,61.24 68.92,68 70.19,69.27 v70.19,69.91 | 68.92,72.13 68.92,78.52 70.19,79.79 v70.19,80.74 70.19,81.38 68.92,82.64 U$1.EXTSEL
N$335  (via drill 1.02)
  other vias: 65.09,30.09
N$336  (via drill 1.02)
  other vias: 62.55,30.09
N$337  (via drill 1.02)
  other vias: 60.01,30.09
N$338  (via drill 1.02)
  other vias: 57.47,30.09
N$339  (via drill 1.02)
  other vias: 54.93,30.09
N$340  (via drill 1.02)
  other vias: 52.39,30.09
N$341  (via drill 1.02)
  other vias: 49.85,30.09
N$342  (via drill 1.02)
  other vias: 47.31,30.09
N$343  (via drill 1.02)
  other vias: 44.77,30.09
N$344  (via drill 1.02)
  other vias: 42.23,30.09
N$345  (via drill 1.02)
  other vias: 39.69,30.09
N$346  (via drill 1.02)
  other vias: 37.15,30.09
N$347  (via drill 1.02)
  other vias: 34.61,30.09
N$348  (via drill 1.02)
  other vias: 32.07,30.09
N$349  (via drill 1.02)
  other vias: 29.53,30.09
N$350  (via drill 1.02)
  other vias: 26.99,30.09
N$351  (via drill 1.02)
  other vias: 24.45,30.09
N$352  (via drill 1.02)
  other vias: 21.91,30.09
N$353  (via drill 1.02)
  other vias: 19.37,30.09
N$354  (via drill 1.02)
  Bottom 0.406: U$3.A0 v11.75,16.72 11.75,17.35 10.48,18.62 10.48,20.21 11.75,21.48 v11.75,27.55
N$355  (via drill 1.02)
  other vias: 16.83,30.09
N$356  (via drill 1.02)  (23 unrouted)
  Bottom 0.406: U$1.A1 66.38,82.64 67.65,81.38 v67.65,80.74 67.65,79.79 66.38,78.52 66.38,71.81 67.67,70.05 67.65,69.27 66.38,68 66.38,61.24 v67.65,59.96 67.65,55.84 | 65.11,55.84 v65.11,59.96 63.84,61.24 63.84,68 65.11,69.27 65.11,70.22 63.84,71.81 63.84,78.52 65.11,79.79 v65.11,80.74 65.11,81.38 63.84,82.64 U$1.A3
  Bottom 1.676: 9.23,56.16 9.23,51.71 | 11.77,56.16 11.77,51.71 | 14.31,56.16 14.31,51.71 | 16.85,56.16 16.85,51.71 | 19.39,56.16 19.39,51.71 | 21.93,56.16 21.93,51.71 | 24.47,56.16 24.47,51.71 | 27.01,56.16 27.01,51.71 | 29.55,56.16 29.55,51.71 | 32.09,56.16 32.09,51.71 | 34.63,56.16 34.63,51.71 | 37.17,56.16 37.17,51.71 | 39.71,56.16 39.71,51.71 | 42.25,56.16 42.25,51.71 | 44.79,56.16 44.79,51.71 | 47.33,56.16 47.33,51.71 | 49.87,56.16 49.87,51.71 | 52.41,56.16 52.41,51.71 | 54.95,56.16 54.95,51.71 | 57.49,56.16 57.49,51.71 | 60.03,56.16 60.03,51.71 | 62.57,56.16 62.57,51.71 | 67.65,56.16 67.65,55.84 67.65,51.71 | 65.11,56.16 65.11,55.84 65.11,51.71
N$357  (via drill 1.02)
  other vias: 14.29,30.09
N$358
  Bottom 0.406: U$1.A5 61.3,82.64
N$359
  Bottom 0.406: U$1.GND5 58.76,82.64
N$360
  Bottom 0.406: U$1.A8 56.22,82.64
N$361
  Bottom 0.406: U$1.A10 53.68,82.64
N$362
  Bottom 0.406: U$1.A12 51.14,82.64
N$363
  Bottom 0.406: U$1.A14 48.6,82.64
N$364
  Bottom 0.406: U$1.A15 46.06,82.64
N$365
  Bottom 0.406: U$1.D1 43.52,82.64
N$366
  Bottom 0.406: U$1.D3 40.98,82.64
N$367
  Bottom 0.406: U$1.D5 38.44,82.64
N$368
  Bottom 0.406: U$1.D7 35.9,82.64
N$369
  Bottom 0.406: U$1.GND4 33.36,82.64
N$370
  Bottom 0.406: U$1.GND3 30.82,82.64
N$371
  Bottom 0.406: U$1.RST 28.28,82.64
N$372
  Bottom 0.406: U$1.RW 13.04,82.64
N$373
  Bottom 0.406: U$1.RAS 15.58,82.64
N$374
  Bottom 0.406: U$1.GND2 18.12,82.64
N$375
  Bottom 0.406: U$1.REF 20.66,82.64
N$376
  Bottom 0.406: U$1.EXT.B 23.2,82.64
N$377
  Bottom 0.406: U$1.RDY 25.74,82.64
N$378
  Bottom 0.406: 61.3,86.34 61.3,82.64 62.57,81.38 62.57,79.79 61.3,78.52
N$379
  Bottom 0.406: 58.76,86.34 58.76,82.64 60.03,81.38 60.03,79.79 58.76,78.52
N$380
  Bottom 0.406: 56.22,86.34 56.22,82.64 57.49,81.38 57.49,79.79 56.22,78.52
N$381
  Bottom 0.406: 53.68,86.34 53.68,82.64 54.95,81.38 54.95,79.79 53.68,78.52
N$382  (via drill 1.02)
  Bottom 0.406: 49.87,83.28 49.87,82.64 51.14,81.38 51.14,79.79 49.87,78.52 49.87,72.13 51.14,70.54 51.14,69.27 49.87,68 v49.87,62.51
N$383
  Bottom 0.406: 51.14,86.34 51.14,82.64 52.41,81.38 52.41,79.79 51.14,78.52
N$384
  Bottom 0.406: 48.6,86.34 48.6,82.64 49.87,81.38 49.87,79.79 48.6,78.52
N$385
  Bottom 0.406: 46.06,86.34 46.06,82.64 47.33,81.38 47.33,79.79 46.06,78.52
N$386
  Bottom 0.406: 43.52,86.34 43.52,82.64 44.79,81.38 44.79,79.79 43.52,78.52
N$387  (via drill 1.02)
  Bottom 0.406: 39.71,83.28 39.71,82.64 40.98,81.38 40.98,79.79 39.71,78.52 39.71,72.13 40.98,70.54 40.98,69.27 39.71,68 v39.71,62.51
N$388
  Bottom 0.406: 40.98,86.34 40.98,82.64 42.25,81.38 42.25,79.79 40.98,78.52
N$389
  Bottom 0.406: 38.44,86.34 38.44,82.64 39.71,81.38 39.71,79.79 38.44,78.52
N$390  (via drill 1.02)  (1 unrouted)
  Bottom 0.406: 34.63,83.28 34.63,82.64 35.9,81.38 35.9,79.79 34.63,78.52 34.63,72.13 35.9,70.54 35.9,69.27 34.63,68 v34.63,62.51
  other vias: 34.63,72.44
N$391
  Bottom 0.406: 35.9,86.34 35.9,82.64 37.17,81.38 37.17,79.79 35.9,78.52
N$392
  Bottom 0.406: 33.36,86.34 33.36,82.64 34.63,81.38 34.63,79.79 33.36,78.52
N$393  (via drill 1.02)
  Bottom 0.406: 29.55,83.28 29.55,82.64 30.82,81.38 30.82,79.79 29.55,78.52 29.55,72.13 30.82,70.54 30.82,69.27 29.55,68 v29.55,62.51
N$394
  Bottom 0.406: 30.82,86.34 30.82,82.64 32.09,81.38 32.09,79.79 30.82,78.52
N$395
  Bottom 0.406: 28.28,86.34 28.28,82.64 29.55,81.38 29.55,79.79 28.28,78.52
N$396  (via drill 1.02)
  Bottom 0.406: 24.47,83.28 24.47,82.64 25.74,81.38 25.74,79.79 24.47,78.52 24.47,72.13 25.74,70.54 25.74,69.27 24.47,68 v24.47,62.51
N$397
  Bottom 0.406: 25.74,86.34 25.74,82.64 27.01,81.38 27.01,79.79 25.74,78.52
N$398
  Bottom 0.406: 23.2,86.34 23.2,82.64 24.47,81.38 24.47,79.79 23.2,78.52
N$399  (via drill 1.02)
  Bottom 0.406: 19.39,83.28 19.39,82.64 20.66,81.38 20.66,79.79 19.39,78.52 19.39,72.13 20.66,70.54 20.66,69.27 19.39,68 v19.39,62.51
N$400
  Bottom 0.406: 20.66,86.34 20.66,82.64 21.93,81.38 21.93,79.79 20.66,78.52
N$401
  Bottom 0.406: 18.12,86.34 18.12,82.64 19.39,81.38 19.39,79.79 18.12,78.52
N$402  (via drill 1.02)  (24 unrouted)
  Top 0.406: v70.19,62.51 68.92,61.24 68.92,59.33 70.19,58.06 70.19,56.16 | v70.19,83.28 70.19,83.01 71.45,81.75 71.45,78.35 72.05,77.75 72.85,77.75 74.15,77.75
  Top 1.676: 70.19,56.16 70.19,51.71 | 65.11,56.16 65.11,51.71 | 62.57,56.16 62.57,51.71 | 60.03,56.16 60.03,51.71 | 57.49,56.16 57.49,51.71 | 54.95,56.16 54.95,51.71 | 52.41,56.16 52.41,51.71 | 49.87,56.16 49.87,51.71 | 47.33,56.16 47.33,51.71 | 44.79,56.16 44.79,51.71 | 42.25,56.16 42.25,51.71 | 39.71,56.16 39.71,51.71 | 37.17,56.16 37.17,51.71 | 34.63,56.16 34.63,51.71 | 32.09,56.16 32.09,51.71 | 29.55,56.16 29.55,51.71 | 27.01,56.16 27.01,51.71 | 24.47,56.16 24.47,51.71 | 21.93,56.16 21.93,51.71 | 19.39,56.16 19.39,51.71 | 16.85,56.16 16.85,51.71 | 14.31,56.16 14.31,51.71 | 11.77,56.16 11.77,51.71 | 9.23,56.16 9.23,51.71
  Bottom 0.406: 70.19,68 70.19,62.82 | 71.46,69.27 71.46,70.86 | 70.19,73.03 70.19,72.8 | 70.19,68 v70.19,62.51 | 71.46,69.27 70.19,68 | 71.46,69.27 71.46,71.17 v70.19,72.44 70.19,73.03 | 70.19,73.03 70.19,78.52 71.46,79.79 71.46,81.69 v70.19,83.28 U$1.GND6
N$403
  Bottom 0.406: 67.65,72.76 67.65,72.13 68.92,70.54 68.92,69.27 67.65,68 67.65,62.82
N$404
  Top 1.016: 11.77,72.76 11.77,70.22
N$405
  Bottom 0.406: 68.92,61.55 68.92,68 70.19,69.27 70.19,70.22 68.92,71.81 68.92,74.07
N$406
  Bottom 0.406: 61.3,78.52 61.3,72.13
N$407
  Bottom 0.406: 58.76,78.52 58.76,72.13
N$408
  Bottom 0.406: 56.22,78.52 56.22,72.13
N$409
  Bottom 0.406: 53.68,78.52 53.68,72.13
N$410
  Bottom 0.406: 51.14,78.52 51.14,72.13
N$411
  Bottom 0.406: 48.6,78.52 48.6,72.13
N$412
  Bottom 0.406: 46.06,78.52 46.06,72.13
N$413
  Bottom 0.406: 43.52,78.52 43.52,72.13
N$414
  Bottom 0.406: 40.98,78.52 40.98,72.13
N$415
  Bottom 0.406: 38.44,78.52 38.44,72.13
N$416
  Bottom 0.406: 35.9,78.52 35.9,72.13
N$417
  Bottom 0.406: 33.36,78.52 33.36,72.13
N$418
  Bottom 0.406: 30.82,78.52 30.82,72.13
N$419
  Bottom 0.406: 28.28,78.52 28.28,72.13
N$420
  Bottom 0.406: 13.04,78.52 13.04,71.81
N$421
  Bottom 0.406: 15.58,78.52 15.58,71.81
N$422
  Bottom 0.406: 18.12,78.52 18.12,72.13
N$423
  Bottom 0.406: 20.66,78.52 20.66,72.13
N$424
  Bottom 0.406: 23.2,78.52 23.2,72.13
N$425
  Bottom 0.406: 25.74,78.52 25.74,72.13
N$426
  Bottom 0.406: U$1.GND 7.96,82.64 9.23,81.38 9.23,79.79 7.96,78.52 7.96,72.13 9.23,70.86 9.23,69.27 7.96,68 7.96,61.24 9.23,59.96 9.23,53.3
N$427  (via drill 1.02)
  Bottom 0.406: 57.49,83.28 57.49,82.64 58.76,81.38 58.76,79.79 57.49,78.52 57.49,72.13 58.76,70.54 58.76,69.27 57.49,68 v57.49,62.51
N$428
  Bottom 0.406: 61.3,78.52 61.3,71.81 62.57,70.22 62.57,69.27 61.3,68 61.3,61.24 62.57,59.96 62.57,53.3
N$429  (via drill 1.02)
  Bottom 0.406: 52.41,83.28 52.41,82.64 53.68,81.38 53.68,79.79 52.41,78.52 52.41,72.13 53.68,70.54 53.68,69.27 52.41,68 v52.41,62.51
N$430  (1 unrouted)
  Bottom 0.406: 56.22,78.52 56.22,71.81 57.49,70.22 57.49,69.27 56.22,68 56.22,61.24 57.49,59.96 57.49,55.84 | 58.76,78.52 58.76,71.81 60.03,70.22 60.03,69.27 58.76,68 58.76,61.24 60.03,59.96 60.03,55.84
N$431
  Bottom 0.406: 53.68,78.52 53.68,71.81 54.95,70.22 54.95,69.27 53.68,68 53.68,61.24 54.95,59.96 54.95,53.3
N$432  (via drill 1.02)
  Bottom 0.406: 47.33,83.28 47.33,82.64 48.6,81.38 48.6,79.79 47.33,78.52 47.33,72.13 48.6,70.54 48.6,69.27 47.33,68 v47.33,62.51
N$433  (1 unrouted)
  Bottom 0.406: 48.6,78.52 48.6,71.81 49.87,70.22 49.87,69.27 48.6,68 48.6,61.24 49.87,59.96 49.87,55.84 | 51.14,78.52 51.14,71.81 52.41,70.22 52.41,69.27 51.14,68 51.14,61.24 52.41,59.96 52.41,55.84
N$434  (via drill 1.02)
  Bottom 0.406: 42.25,83.28 42.25,82.64 43.52,81.38 43.52,79.79 42.25,78.52 42.25,72.13 43.52,70.54 43.52,69.27 42.25,68 v42.25,62.51
N$435  (via drill 1.02)
  Bottom 0.406: 44.79,83.28 44.79,82.64 46.06,81.38 46.06,79.79 44.79,78.52 44.79,72.13 46.06,70.54 46.06,69.27 44.79,68 v44.79,62.51
N$436
  Bottom 0.406: 46.06,78.52 46.06,71.81 47.33,70.22 47.33,69.27 46.06,68 46.06,61.24 47.33,59.96 47.33,53.3
N$437  (via drill 1.02)
  Bottom 0.406: 37.17,83.28 37.17,82.64 38.44,81.38 38.44,79.79 37.17,78.52 37.17,72.13 38.44,70.54 38.44,69.27 37.17,68 v37.17,62.51
N$438  (1 unrouted)
  Bottom 0.406: 40.98,78.52 40.98,71.81 42.25,70.22 42.25,69.27 40.98,68 40.98,61.24 42.25,59.96 42.25,55.84 | 43.52,78.52 43.52,71.81 44.79,70.22 44.79,69.27 43.52,68 43.52,61.24 44.79,59.96 44.79,55.84
N$439
  Bottom 0.406: 38.44,78.52 38.44,71.81 39.71,70.22 39.71,69.27 38.44,68 38.44,61.24 39.71,59.96 39.71,53.3
N$440  (via drill 1.02)
  Bottom 0.406: 32.09,83.28 32.09,82.64 33.36,81.38 33.36,79.79 32.09,78.52 32.09,72.13 33.36,70.54 33.36,69.27 32.09,68 v32.09,62.51
N$441  (1 unrouted)
  Bottom 0.406: 33.36,78.52 33.36,71.81 34.63,70.22 34.63,69.27 33.36,68 33.36,61.24 34.63,59.96 34.63,55.84 | 35.9,78.52 35.9,71.81 37.17,70.22 37.17,69.27 35.9,68 35.9,61.24 37.17,59.96 37.17,55.84
N$442  (via drill 1.02)
  Bottom 0.406: 27.01,83.28 27.01,82.64 28.28,81.38 28.28,79.79 27.01,78.52 27.01,72.13 28.28,70.54 28.28,69.27 27.01,68 v27.01,62.51
N$443
  Bottom 0.406: 30.82,78.52 30.82,71.81 32.41,69.91 32.09,69.27 30.82,68 30.82,61.24 32.09,59.96 32.09,53.3
N$444  (via drill 1.02)
  Bottom 0.406: 21.93,72.44 21.93,72.76 | 21.93,72.44 21.93,72.13 23.2,70.54 23.2,69.27 21.93,68 v21.93,62.51 | 21.93,83.28 21.93,82.64 23.2,81.38 23.2,79.79 21.93,78.52 21.93,72.44
N$445  (1 unrouted)
  Bottom 0.406: 25.74,78.52 25.74,71.81 27.01,70.22 27.01,69.27 25.74,68 25.74,61.24 27.01,59.96 27.01,55.84 | 28.28,78.52 28.28,71.81 29.55,70.22 29.55,69.27 28.28,68 28.28,61.24 29.55,59.96 29.55,55.84
N$446
  Bottom 0.406: 23.2,78.52 23.2,71.81 24.47,70.22 24.47,69.27 23.2,68 23.2,61.24 24.47,59.96 24.47,53.3
N$447  (via drill 1.02)  (6 unrouted)
  Bottom 0.406: 15.58,71.81 16.85,70.22 16.85,69.27 15.58,68 15.58,61.24 16.85,59.96 16.85,53.3 | 13.04,71.81 14.31,70.22 14.31,69.27 13.04,68 13.04,61.24 14.31,59.96 14.31,55.84 | 16.85,83.28 16.85,82.64 18.12,81.38 18.12,79.79 16.85,78.52 16.85,72.13 18.12,70.54 18.12,69.27 16.85,68 v16.85,62.51 | 15.58,82.64 16.85,81.38 16.85,79.79 15.58,78.52 | 14.31,82.64 15.58,81.38 15.58,79.79 14.31,78.52 14.31,72.13 15.58,70.54 15.58,69.27 14.31,68 v14.31,62.51 | 13.04,82.64 14.31,81.38 14.31,79.79 13.04,78.52 | 11.77,59.96 11.77,55.84
N$448  (1 unrouted)
  Bottom 0.406: 18.12,78.52 18.12,71.81 19.39,70.22 19.39,69.27 18.12,68 18.12,61.24 19.39,59.96 19.39,55.84 | 20.66,78.52 20.66,71.81 21.93,70.22 21.93,69.27 20.66,68 20.66,61.24 21.93,59.96 21.93,55.84
S$1  (1 unrouted)
S$2
  Top 0.406: 2.55,22.35 2.55,26.25
S$3
  Bottom 1.676: 9.21,43.84 9.21,48.28
S$4
  Bottom 1.676: 70.19,56.16 70.19,51.71
S$5  (via drill 1.02)
  other vias: 70.19,59.96
S$6  (via drill 1.02)
  other vias: 9.21,40.03
S$7  (via drill 1.02)
  other vias: 62.57,80.74
S$8  (via drill 1.02)
  other vias: 16.83,19.25
S$9  (via drill 1.02)
  other vias: 19.37,19.25
S$10  (via drill 1.02)
  other vias: 60.03,80.74
S$11  (via drill 1.02)
  other vias: 21.91,19.25
S$12  (via drill 1.02)
  other vias: 57.49,80.74
S$13  (via drill 1.02)
  other vias: 24.45,19.25
S$14  (via drill 1.02)
  other vias: 54.95,80.74
S$15  (via drill 1.02)
  other vias: 26.99,19.25
S$16  (via drill 1.02)
  other vias: 52.41,80.74
S$17  (via drill 1.02)
  other vias: 29.53,19.25
S$18  (via drill 1.02)
  other vias: 49.87,80.74
S$19  (via drill 1.02)
  other vias: 32.07,19.25
S$20  (via drill 1.02)
  other vias: 47.33,80.74
S$21  (via drill 1.02)
  other vias: 34.61,19.25
S$22  (via drill 1.02)
  other vias: 44.79,80.74
S$23  (via drill 1.02)
  other vias: 37.15,19.25
S$24  (via drill 1.02)
  other vias: 39.69,19.25
S$25  (via drill 1.02)
  other vias: 42.23,19.25
S$26  (via drill 1.02)
  other vias: 44.77,19.25
S$27  (via drill 1.02)
  other vias: 47.31,19.25
S$28  (via drill 1.02)
  other vias: 49.85,19.25
S$29  (via drill 1.02)
  other vias: 65.09,19.25
S$30  (via drill 1.02)
  other vias: 62.55,19.25
S$31  (via drill 1.02)
  other vias: 60.01,19.25
S$32  (via drill 1.02)
  other vias: 57.47,19.25
S$33  (via drill 1.02)
  other vias: 54.93,19.25
S$34  (via drill 1.02)
  other vias: 52.39,19.25
S$35  (via drill 1.02)
  other vias: 70.17,19.25
S$36  (via drill 1.02)
  other vias: 42.25,80.74
S$37  (via drill 1.02)
  other vias: 39.71,80.74
S$38  (via drill 1.02)
  other vias: 37.17,80.74
S$39  (via drill 1.02)
  other vias: 34.63,80.74
S$40  (via drill 1.02)
  other vias: 32.09,80.74
S$41  (via drill 1.02)
  other vias: 29.55,80.74
S$42  (via drill 1.02)
  other vias: 14.31,80.74
S$43  (via drill 1.02)
  other vias: 16.85,80.74
S$44  (via drill 1.02)
  other vias: 19.39,80.74
S$45  (via drill 1.02)
  other vias: 21.93,80.74
S$46  (via drill 1.02)
  other vias: 24.47,80.74
S$47  (via drill 1.02)
  other vias: 27.01,80.74
S$48  (via drill 1.02)
  other vias: 9.23,80.74
S$49  (1 unrouted)
S$50
  Top 0.406: 76.85,77.65 76.85,73.75
S$55
  Top 0.406: 65.25,51.55 65.2,51.5
S$56
  Top 0.406: 67.9,48.7 67.7,48.5
S$57
  Top 0.406: 70,51.6 70.05,51.55
(copper drawn outside any net)
  shapes: Bottom area x2, Top area x2

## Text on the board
Top: 1 | 49 | 2 | K | A | 50 | for ABBUC-FREEZER 2011 | ATARI 600/800XL PBI Adapter | 1K | 49 | 1 | +5V | 50 | 50 | 2 | (C)2011 ABBUC/MEGA-HZ | 49 | 1 | 50 | 2 | 1 | 49 | 49 | 1 | 2 | 50 | 49 | 1 | (C)2011 ABBUC/MEGA-HZ | 2 | 50 | 50 | +5V | 1 | 49 | 1K | ATARI 600/800XL PBI Adapter | for ABBUC-FREEZER 2011 | 50 | A | K | 2 | 49 | 1
Bottom: 2 | 50 | 50 | 2
tStop: 1 | 49 | 2 | K | A | 50 | for ABBUC-FREEZER 2011 | ATARI 600/800XL PBI Adapter | 1K | 49 | 1 | +5V | 50 | 2 | (C)2011 ABBUC/MEGA-HZ | 49 | 1 | 50 | 2 | 2 | 50 | 49 | 1 | (C)2011 ABBUC/MEGA-HZ | 2 | 50 | +5V | 1 | 49 | 1K | ATARI 600/800XL PBI Adapter | for ABBUC-FREEZER 2011 | 50 | A | K | 2 | 49 | 1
